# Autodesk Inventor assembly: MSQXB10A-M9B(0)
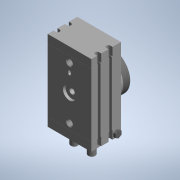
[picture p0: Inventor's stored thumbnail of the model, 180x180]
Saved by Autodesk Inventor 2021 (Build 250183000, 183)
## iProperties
Category: PARTsolutions
Part Number: MSQXB10A-M9B(0)
Catalog Web Link: www.cadenas.de
Description: MSQX-Low-Speed Rotary Table Rack & Pinion Style
Document SubType Name: Assembly
Designer: partserver
Mass: 168.018 g
Surface Area: 337.625 cm^2
Volume: 168.018 cm^3
Density: 1 g/cm^3
PSOL_IDENT_0: {$CADENAS_DATA\23d-libs\smc_jp\actuator\rotary_actuator\msqx\msqx_asmtab.prj},218 {VTYP=3D},{STYP=AS
PSOL_IDENT_1: STAB},{NB=MSQXB10A-M9B(0)},{LINA=MSQXB10A-M9B},{NN=MSQX},{DATE=09.12.2020 02:49:37},{GEOMDATE=09.03.
PSOL_IDENT_2: 2020 10:24:15},{VERSION=},{LINEID=160},{WBVAR=THREAD1,AUTOSW,LEAD,NUMBER,OMSC,THREAD},{WBNUMERIC=}
PSOL_IDENT_3: {NB=MSQXB10A-M9B(0)},{LINA=MSQXB10A-M9B},{KT=DUMMY},{ORDER=MSQXB10A-M9B},{SIZE=10},{THREAD1=},{AUTOS
PSOL_IDENT_4: W=-M9B},{LEAD=},{LEADX= '','(-) 0.5 m' , 'M','(M) 1 m' , 'L','(L) 3 m' , 'Z','(Z) 5 m' },{NUMBER=},{
PSOL_IDENT_5: SWSIGNX= '','(-) 2 pcs' , 'S','(S) 1 pc' },{PORTX= '', '(-) M5' },{OMSC=},{THREAD=0},{NENN=MSQXB10},
PSOL_IDENT_6: {MODEL=MSQXB10A-M9B},{X=},{TIF=1},{AA=55.4},{A=50},{AU=8.6},{AV=20.0},{AW=15.5},{AX=12},{AY=4},{BA=9
PSOL_IDENT_7: .5},{BB=34.5},{BC=27.8},{BD=60},{BE=27},{CA=4.5},{CB=28.5},{D=45h9},{D1=45},{DD=46h9},{DD1=46},{DE=2
PSOL_IDENT_8: 0H9},{DE1=20},{DF=6},{DG=15H9},{DG1=15},{FA=8.0},{FB=4.0},{FC=3.0},{FD=4.5},{H=13},{J=6.8},{JA=11.0}
PSOL_IDENT_9: ,{JB=6.5},{JC=M8x1.25},{JC1=8},{JCP=1.25},{JD=12},{JJ=M5x0.8},{JJ1=5},{JJP=0.80},{JU=M8x1},{JU1=8},{
PSOL_IDENT_10: JUP=1.0},{P=M5x0.8},{P1=5.000},{PP=0.8},{Q=34},{S=92},{SD=9.0},{SE=13},{SF=45},{SU=17.7},{UU=47},{WA=
PSOL_IDENT_11: 15.0},{WB=3H9},{WB1=3},{WC=3.5},{WD=M5x0.8},{WD1=5},{WDP=0.80},{WE=8.0},{WF=32},{XA=27},{XB=3H9},{XB
PSOL_IDENT_12: 1=3},{XC=3.5},{YA=19},{YB=3H9},{YB1=3},{YC=3.5},{F1=6.917},{F2=5},{Y1=8},{Y2=12},{H1=5.000},{H2=5.00
PSOL_IDENT_13: 0},{SWA=61},{SWB=43},{PD=0.3},{EA=47.1},{EB=44.3},{EC=33.5},{ED=14.0},{EE=91.4},{EF=80},{GA=20},{GB=
PSOL_IDENT_14: 15.6},{GC=11},{GD=7.5},{GE=45.2},{K=M8x1},{NA=10.0},{MB=5.5},{NC=12.5},{ND=4},{PPATH=assembly/msqx_a
PSOL_IDENT_15: smsbl.prj}
NB: MSQXB10A-M9B(0)
NN: MSQX
NT: Low-Speed Rotary Table Rack & Pinion Style
NBSYN: $ORDER.($THREAD.)
LINA: MSQXB10A-M9B
CATALOG: SMC (JP
ROWDESC: MSQXB10
SIZE: 10
THREAD1: (-) M5
AUTOSW: M9B Solid state-General-Grommet-Indicator light:Yes-2 wire-In line
LEAD: (-) 0.5 m
NUMBER: (-) 2 pcs
OMSC: (-) Without order
THREAD: on
ARTICLENO: MSQXB10A-M9B(0)
BOMINFO: MSQXB10A-M9B
CREATOR: CADENAS GmbH
Title: MSQXB10A-M9B
Author: Cadenas PARTsolutions
Comments: Low-Speed Rotary Table Rack & Pinion Style
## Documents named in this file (5)
- D:\01 Paralaia\Grupos de Traballo\GT Maquetas\CAD 3D\E_Medida\SMC_JP_MSQXB10AM9B0\MSQXB10A-M9B(0).iam
- D:\01 Paralaia\Grupos de Traballo\GT Maquetas\CAD 3D\E_Medida\SMC_JP_MSQXB10AM9B0\MSQX10(0)_BODY.ipt
- D:\01 Paralaia\Grupos de Traballo\GT Maquetas\CAD 3D\E_Medida\SMC_JP_MSQXB10AM9B0\MSQX10(0)_Table.ipt
- D:\01 Paralaia\Grupos de Traballo\GT Maquetas\CAD 3D\E_Medida\SMC_JP_MSQXB10AM9B0\MSQX_M-5P.ipt
- D:\01 Paralaia\Grupos de Traballo\GT Maquetas\CAD 3D\E_Medida\SMC_JP_MSQXB10AM9B0\D-M9B_MSQX.ipt
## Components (6 placed, 4 different names)
1. MSQX10(0)_BODY:1 — Insertar:1
2. MSQX10(0)_Table:1 — Insertar:1
3. MSQX_M-5P:1
4. MSQX_M-5P:2
5. D-M9B_MSQX:1
6. D-M9B_MSQX:2
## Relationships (1: Insert 1)
- Insertar:1: MSQX10(0)_BODY:1 ↔ MSQX10(0)_Table:1
